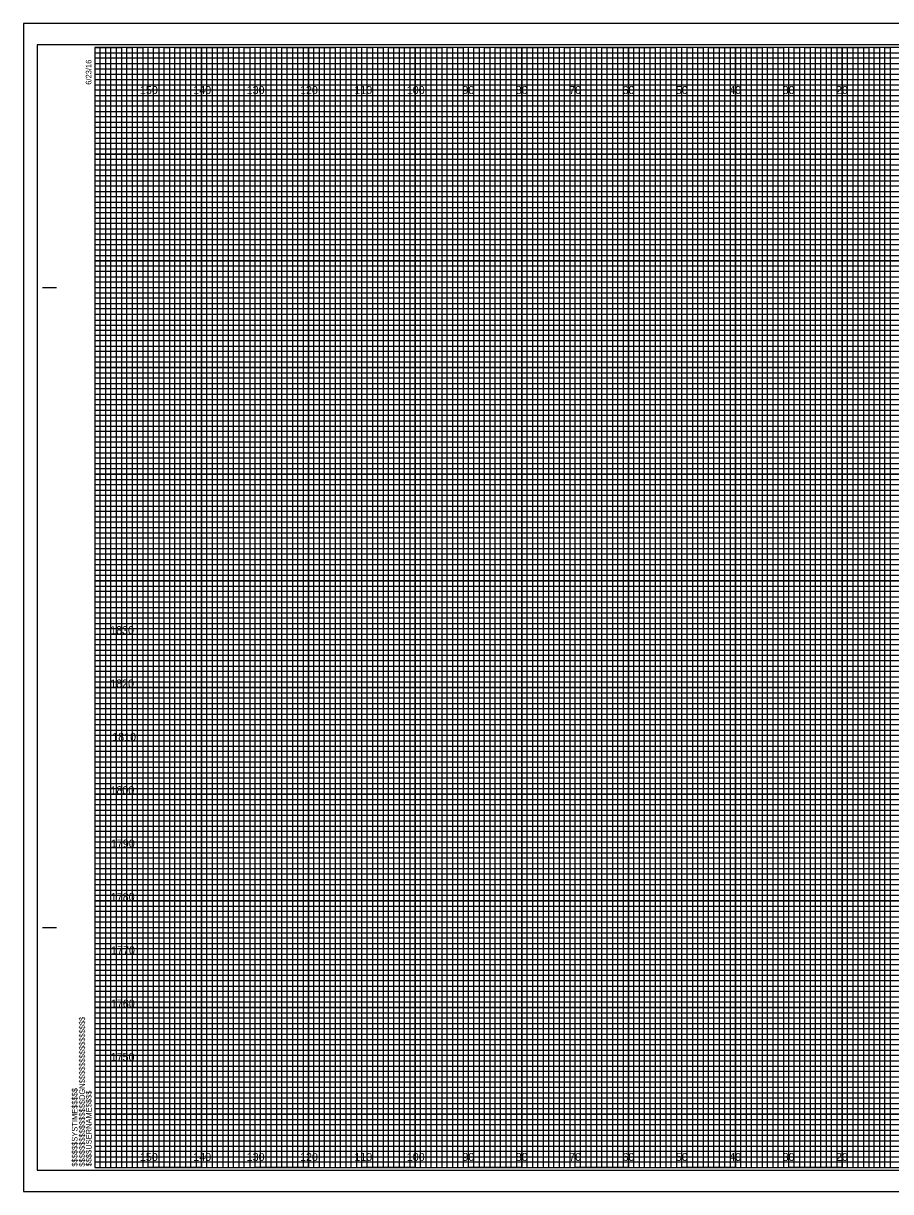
# Model space of a CAD drawing. Extents: x -13 to 323, y -5 to 654.
# Drawn here: x -13.4 to 149.1, y 435.5 to 654.5 of the extents above; entities that cross this region are included whole.
import ezdxf

# ---------------------------------------------------------------- set-up
doc = ezdxf.new("R2010")
doc.units = 0
for name, color, linetype in [('Prop XS DDE', 7, 'Continuous'), ('Prop XS Earthwork Shape', 7, 'Continuous'), ('Raster_Level_0', 7, 'Continuous'), ('Scratch_Level_3', 7, 'Continuous'), ('Sheet Cross Section CELL', 7, 'Continuous'), ('Sheet Cross Section Grid Minor 1 CELL', 7, 'Continuous'), ('Sheet Cross Section Grid Minor 2 CELL', 7, 'Continuous'), ('Sheet Cutting Line CELL', 7, 'Continuous'), ('Sheet DOT Grid CELL', 7, 'Continuous'), ('Sheet Plot Border Inside CELL', 7, 'Continuous'), ('Sheet Plot Border Outside CELL', 7, 'Continuous')]:
    doc.layers.add(name, color=color, linetype=linetype)

msp = doc.modelspace()

# ---------------------------------------------------------------- linework, layer by layer
at = {"layer": 'Prop XS DDE'}
for points in [[(0, 650), (5, 650), (5, 440), (15, 440), (15, 650), (25, 650), (25, 440), (35, 440), (35, 650), (45, 650), (45, 440), (55, 440), (55, 650), (65, 650), (65, 440), (75, 440), (75, 650), (85, 650), (85, 440), (95, 440), (95, 650), (105, 650), (105, 440), (115, 440), (115, 650), (125, 650), (125, 440), (135, 440), (135, 650), (145, 650), (145, 440), (155, 440)], [(0, 645), (275, 645)], [(0, 625), (320, 625), (320, 635), (0, 635)], [(0, 605), (320, 605), (320, 615), (0, 615)], [(0, 585), (320, 585), (320, 595), (0, 595)], [(0, 565), (320, 565), (320, 575), (0, 575)], [(0, 545), (320, 545), (320, 555), (0, 555)], [(0, 525), (320, 525), (320, 535), (0, 535)], [(0, 505), (320, 505), (320, 515), (0, 515)], [(0, 485), (320, 485), (320, 495), (0, 495)], [(0, 465), (320, 465), (320, 475), (0, 475)], [(0, 445), (320, 445), (320, 455), (0, 455)]]:
    msp.add_lwpolyline(points, dxfattribs=at)
at = {"layer": 'Prop XS Earthwork Shape'}
for p, q in [((10, 650), (0, 650)), ((10, 440), (10, 650)), ((30, 650), (20, 650)), ((20, 650), (20, 440)), ((30, 440), (30, 650)), ((50, 650), (40, 650)), ((40, 650), (40, 440)), ((50, 440), (50, 650)), ((70, 650), (60, 650)), ((60, 650), (60, 440)), ((70, 440), (70, 650)), ((90, 650), (80, 650)), ((80, 650), (80, 440)), ((90, 440), (90, 650)), ((110, 650), (100, 650)), ((100, 650), (100, 440)), ((110, 440), (110, 650)), ((130, 650), (120, 650)), ((120, 650), (120, 440)), ((130, 440), (130, 650)), ((150, 650), (140, 650)), ((140, 650), (140, 440)), ((20, 440), (10, 440)), ((40, 440), (30, 440)), ((60, 440), (50, 440)), ((80, 440), (70, 440)), ((100, 440), (90, 440)), ((120, 440), (110, 440)), ((140, 440), (130, 440))]:
    msp.add_line(p, q, dxfattribs=at)
for points in [[(0, 640), (320, 640), (320, 630), (0, 630)], [(0, 620), (320, 620), (320, 610), (0, 610)], [(0, 600), (320, 600), (320, 590), (0, 590)], [(0, 580), (320, 580), (320, 570), (0, 570)], [(0, 560), (320, 560), (320, 550), (0, 550)], [(0, 540), (320, 540), (320, 530), (0, 530)], [(0, 520), (320, 520), (320, 510), (0, 510)], [(0, 500), (320, 500), (320, 490), (0, 490)], [(0, 480), (320, 480), (320, 470), (0, 470)], [(0, 460), (320, 460), (320, 450), (0, 450)]]:
    msp.add_lwpolyline(points, dxfattribs=at)
at = {"layer": 'Sheet Cross Section CELL'}
for p, q in [((-9.8, 605), (-7.3, 605)), ((-9.7, 605), (-7.2, 605)), ((-9.8, 485), (-7.3, 485)), ((-9.7, 485), (-7.2, 485)), ((0, 440), (0, 440)), ((0, 440), (0, 440)), ((0, 440), (0, 440)), ((0, 440), (0, 440)), ((0, 440), (0, 440)), ((0, 440), (0, 440)), ((0, 440), (0, 440))]:
    msp.add_line(p, q, dxfattribs=at)
msp.add_lwpolyline([(320, 650), (0, 650), (0, 440), (320, 440)], close=True, dxfattribs=at)
at = {"layer": 'Sheet Cross Section Grid Minor 1 CELL'}
for p, q in [((0, 649), (260, 649)), ((260, 647.98), (0, 647.98)), ((0, 647.98), (0, 647)), ((0, 647), (260, 647)), ((260, 645.89), (0, 645.89)), ((0, 645.89), (0, 644)), ((0, 644), (320, 644))]:
    msp.add_line(p, q, dxfattribs=at)
for points in [[(0, 643), (270, 643), (320, 643), (320, 642), (0, 642)], [(0, 641), (320, 641), (320, 639), (0, 639)], [(0, 638), (320, 638), (320, 637), (0, 636.98)], [(0, 636), (320, 636), (320, 634), (0, 634)], [(0, 633), (320, 633), (320, 632), (0, 632)], [(0, 631), (320, 631), (320, 629), (0, 629)], [(0, 628), (320, 628), (320, 627), (0, 627)], [(0, 626), (320, 626), (320, 624), (0, 624)], [(0, 623), (320, 623), (320, 622), (0, 622)], [(0, 621), (320, 621), (320, 619), (0, 619)], [(0, 618), (320, 618), (320, 617), (0, 617)], [(0, 616), (320, 616), (320, 613.95), (320, 613), (320, 612), (0, 612)], [(0, 614), (320, 614), (320, 613), (0, 613)], [(0, 611), (320, 611), (320, 609), (0, 609.03)], [(0, 609.03), (320, 609), (320, 608), (0, 608)], [(0, 607), (320, 607), (320, 606), (0, 606)], [(0, 604), (320, 604), (320, 603), (0, 603)], [(0, 602), (320, 602), (320, 601), (0, 601)], [(-0.07, 598.89), (320, 598.89), (320, 597.88), (-0.07, 597.88)], [(0, 597), (320, 597), (320, 596), (0, 596)], [(0, 594), (320, 594), (320, 593), (0, 593)], [(0, 592), (320, 592), (320, 591), (0, 591)], [(0, 589), (320, 589), (320, 588), (0, 588)], [(0, 587), (320, 587), (320, 586), (0, 586)], [(0, 584), (320, 584), (320, 583), (0, 583)], [(0, 582), (320, 582), (320, 581), (0, 581)], [(0, 579), (320, 579), (319.99, 577.98), (0, 578)], [(0, 577), (320, 577), (320, 576), (0, 576)], [(0, 574), (320, 574), (320, 573), (0, 573)], [(0, 572), (320, 572), (320, 571), (0, 571)], [(0, 569), (320, 569), (320, 568), (0, 568)], [(0, 567), (320, 567), (320, 566), (0, 566)], [(0, 564), (320, 564), (320, 563), (0, 563)], [(0, 562), (320, 562), (320, 561), (0, 561)], [(0, 559), (320, 559), (320, 558), (0, 558)], [(0, 556.99), (320.07, 556.91), (320, 556), (0, 556)], [(0, 554), (320, 554), (320, 553), (0, 553)], [(0, 552), (320, 552), (320, 551), (0, 551)], [(0, 549), (320, 549), (320, 548), (0, 548)], [(0, 547), (320, 547), (320, 546), (0, 546)], [(0, 544), (320, 544), (320, 543), (0, 543)], [(0, 542), (320, 542), (320, 541), (0, 541)], [(0, 539), (320, 539), (320, 538), (0, 538)], [(0, 537), (320, 537), (320, 536), (0, 536)], [(0, 534), (320, 534), (320, 533), (0, 533)], [(0, 532), (320, 532), (320, 531), (0, 531)], [(0, 529), (320, 529), (320, 528), (0, 528)], [(0, 527), (320, 527), (320, 526), (0, 526)], [(0, 524), (320, 524), (320, 523), (0, 523)], [(0, 522), (320, 522), (320, 521), (0, 521)], [(0, 519), (320, 519), (319.99, 517.98), (0, 518)], [(0, 517), (320, 517), (320, 516), (0, 516)], [(0, 514), (320, 514), (320, 513), (0, 513)], [(0, 512), (320, 512), (320, 511), (0, 511)], [(0, 509), (320, 509), (320, 508), (0, 508)], [(0, 507), (320, 507), (320, 506), (0, 506)], [(0, 504), (320, 504), (320, 503), (0, 503)], [(0, 502), (320, 502), (320, 501), (0, 501)], [(0, 499), (320, 499), (320, 498), (0, 498)], [(0, 496.99), (320.07, 496.91), (320, 496), (0, 496)], [(0, 494), (320, 494), (320, 493), (0, 493)], [(0, 492), (320, 492), (320, 491), (0, 491)], [(0, 489), (320, 489), (320, 488), (0, 488)], [(0, 487), (320, 487), (320, 486), (0, 486)], [(0, 484), (320, 484), (320, 483), (0, 483)], [(0, 482), (320, 482), (320, 481), (0, 481)], [(0, 479), (320, 479), (320, 478), (0, 478)], [(0, 477), (320, 477), (320, 476), (0, 476)], [(0, 474), (320, 474), (320, 473), (0, 473)], [(0, 472), (320, 472), (320, 471), (0, 471)], [(0, 469), (320, 469), (320, 468), (0, 468)], [(0, 467), (320, 467), (320, 466), (0, 466)], [(0, 464), (320, 464), (320, 463), (0, 463)], [(0, 462), (320, 462), (320, 461), (0, 461)], [(0, 459), (320, 459), (320, 458), (0, 458)], [(0, 457), (320, 457), (320, 456), (0, 456)], [(0, 454), (320, 454), (320, 453), (0, 453)], [(0, 452), (320, 452), (320, 451), (0, 451)], [(0, 449), (320, 449), (320, 448), (0, 448)], [(0, 447), (320, 447), (320, 446), (0, 446)], [(0, 444), (320, 444), (320, 443), (0, 443)], [(0, 442), (320, 442), (320, 441), (0, 441)]]:
    msp.add_lwpolyline(points, dxfattribs=at)
at = {"layer": 'Sheet Cross Section Grid Minor 2 CELL'}
for points in [[(0, 440), (1, 440), (1, 650), (2, 650), (2, 440)], [(2, 440), (3, 440), (3, 650), (4, 650), (4, 440)], [(5, 440), (6, 440), (6, 650), (7, 650), (7, 440)], [(7, 440), (8, 440), (8, 650), (9, 650), (9, 440)], [(10, 440), (11, 440), (11, 650), (12, 650), (12, 440)], [(12, 440), (13, 440), (13, 650), (14, 650), (14, 440)], [(15, 440), (16, 440), (16, 650), (17, 650), (17, 440)], [(17, 440), (18, 440), (18, 650), (19, 650), (19, 440)], [(20, 440), (21, 440), (21, 650), (22, 650), (22, 440)], [(22, 440), (23, 440), (23, 650), (24, 650), (24, 440)], [(25, 440), (26, 440), (26, 650), (27, 650), (27, 440)], [(27, 440), (28, 440), (28, 650), (29, 650), (29, 440)], [(30, 440), (31, 440), (31, 650), (32, 650), (32, 440)], [(32, 440), (33, 440), (33, 650), (34, 650), (34, 440)], [(35, 440), (36, 440), (36, 650), (37, 650), (37, 440)], [(37, 440), (38, 440), (38, 650), (39, 650), (39, 440)], [(40, 440), (41, 440), (41, 650), (42, 650), (42, 440)], [(42, 440), (43, 440), (43, 650), (44, 650), (44, 440)], [(45, 440), (46, 440), (46, 650), (47, 650), (47, 440)], [(47, 440), (48, 440), (48, 650), (49, 650), (49, 440)], [(50, 440), (51, 440), (51, 650), (52, 650), (52, 440)], [(52, 440), (53, 440), (53, 650), (54, 650), (54, 440)], [(55, 440), (56, 440), (56, 650), (57, 650), (57, 440)], [(57, 440), (58, 440), (58, 650), (59, 650), (59, 440)], [(60, 440), (61, 440), (61, 650), (62, 650), (62, 440)], [(62, 440), (63, 440), (63, 650), (64, 650), (64, 440)], [(65, 440), (66, 440), (66, 650), (67, 650), (67, 440)], [(67, 440), (68, 440), (68, 650), (69, 650), (69, 440)], [(70, 440), (71, 440), (71, 650), (72, 650), (72, 440)], [(72, 440), (73, 440), (73, 650), (74, 650), (74, 440)], [(75, 440), (76, 440), (76, 650), (77, 650), (77, 440)], [(77, 440), (78, 440), (78, 650), (79, 650), (79, 440)], [(80, 440), (81, 440), (81, 650), (82, 650), (82, 440)], [(82, 440), (83, 440), (83, 650), (84, 650), (84, 440)], [(85, 440), (86, 440), (86, 650), (87, 650), (87, 440)], [(87, 440), (88, 440), (88, 650), (89, 650), (89, 440)], [(90, 440), (91, 440), (91, 650), (92, 650), (92, 440)], [(92, 440), (93, 440), (93, 650), (94, 650), (94, 440)], [(95, 440), (96, 440), (96, 650), (97, 650), (97, 440)], [(97, 440), (98, 440), (98, 650), (99, 650), (99, 440)], [(100, 440), (101, 440), (101, 650), (102, 650), (102, 440)], [(102, 440), (103, 440), (103, 650), (104, 650), (104, 440)], [(105, 440), (106, 440), (106, 650), (107, 650), (107, 440)], [(107, 440), (108, 440), (108, 650), (109, 650), (109, 440)], [(110, 440), (111, 440), (111, 650), (112, 650), (112, 440)], [(112, 440), (113, 440), (113, 650), (114, 650), (114, 440)], [(115, 440), (116, 440), (116, 650), (117, 650), (117, 440)], [(117, 440), (118, 440), (118, 650), (119, 650), (119, 440)], [(120, 440), (121, 440), (121, 650), (122, 650), (122, 440)], [(122, 440), (123, 440), (123, 650), (124, 650), (124, 440)], [(125, 440), (126, 440), (126, 650), (127, 650), (127, 440)], [(127, 440), (128, 440), (128, 650), (129, 650), (129, 440)], [(130, 440), (131, 440), (131, 650), (132, 650), (132, 440)], [(132, 440), (133, 440), (133, 650), (134, 650), (134, 440)], [(135, 440), (136, 440), (136, 650), (137, 650), (137, 440)], [(137, 440), (138, 440), (138, 650), (139, 650), (139, 440)], [(140, 440), (141, 440), (141, 650), (142, 650), (142, 440)], [(142, 440), (143, 440), (143, 650), (144, 650), (144, 440)], [(145, 440), (146, 440), (146, 650), (147, 650), (147, 440)], [(147, 440), (148, 440), (148, 650), (149, 650), (149, 440)]]:
    msp.add_lwpolyline(points, dxfattribs=at)
at = {"layer": 'Sheet Cutting Line CELL'}
for p, q in [((323.3, 654.5), (-13.4, 654.5)), ((-13.4, 654.5), (-13.4, 435.5)), ((-13.4, 435.5), (323.3, 435.5))]:
    msp.add_line(p, q, dxfattribs=at)
at = {"layer": 'Sheet DOT Grid CELL'}
for p, q in [((10, 440), (10, 650)), ((20, 440), (20, 650)), ((30, 440), (30, 650)), ((40, 440), (40, 650)), ((50, 440), (50, 650)), ((60, 440), (60, 650)), ((70, 440), (70, 650)), ((80, 440), (80, 650)), ((90, 440), (90, 650)), ((100, 440), (100, 650)), ((110, 440), (110, 650)), ((120, 440), (120, 650)), ((130, 440), (130, 650)), ((140, 440), (140, 650)), ((0, 640), (320, 640)), ((0, 630), (320, 630)), ((0, 620), (320, 620)), ((0, 610), (320, 610)), ((0, 600), (320, 600)), ((0, 590), (320, 590)), ((0, 580), (320, 580)), ((0, 570), (320, 570)), ((0, 560), (320, 560)), ((0, 550), (320, 550)), ((0, 540), (320, 540)), ((0, 530), (320, 530)), ((0, 520), (320, 520)), ((0, 510), (320, 510)), ((0, 500), (320, 500)), ((0, 490), (320, 490)), ((0, 480), (320, 480)), ((0, 470), (320, 470)), ((0, 460), (320, 460)), ((0, 450), (320, 450))]:
    msp.add_line(p, q, dxfattribs=at)
at = {"layer": 'Sheet Plot Border Inside CELL'}
msp.add_lwpolyline([(-10.8, 439.5), (322.4, 439.5), (322.4, 650.5), (-10.8, 650.5)], close=True, dxfattribs=at)
at = {"layer": 'Sheet Plot Border Outside CELL'}
msp.add_lwpolyline([(-13.4, 435.5), (323.3, 435.5), (323.3, 654.5), (-13.4, 654.5)], close=True, dxfattribs=at)

# ---------------------------------------------------------------- texts
at = {"layer": 'Raster_Level_0'}
for s, p in [('150', (8.44, 641.25)), ('140', (18.44, 641.25)), ('130', (28.44, 641.25)), ('120', (38.44, 641.25)), ('110', (48.62, 641.25)), ('100', (58.44, 641.25)), ('90', (68.86, 641.25)), ('80', (78.86, 641.25)), ('70', (88.86, 641.25)), ('60', (98.86, 641.25)), ('50', (108.86, 641.25)), ('40', (118.86, 641.25)), ('30', (128.86, 641.25)), ('20', (138.86, 641.25)), ('150', (8.44, 441.25)), ('140', (18.44, 441.25)), ('130', (28.44, 441.25)), ('120', (38.44, 441.25)), ('110', (48.62, 441.25)), ('100', (58.44, 441.25)), ('90', (68.86, 441.25)), ('80', (78.86, 441.25)), ('70', (88.86, 441.25)), ('60', (98.86, 441.25)), ('50', (108.86, 441.25)), ('40', (118.86, 441.25)), ('30', (128.86, 441.25)), ('20', (138.86, 441.25))]:
    msp.add_text(s, height=1.5, dxfattribs=at).set_placement(p)
at = {"layer": 'Scratch_Level_3'}
for s, p in [('1830', (2.86, 540)), ('1820', (2.87, 530)), ('1810', (3.25, 520)), ('1800', (2.92, 510)), ('1790', (3, 500)), ('1780', (2.98, 490)), ('1770', (3.04, 480)), ('1760', (3, 470)), ('1750', (2.96, 460))]:
    msp.add_text(s, height=1.5, dxfattribs=at).set_placement(p)
at = {"layer": 'Sheet Cross Section CELL'}
for s, p in [('6/23/16', (-0.65, 643)), ('$$$$$$$$$$$$$$$$DGN$$$$$$$$$$$$$$$$', (-1.88, 440.18)), ('$$$$$$SYSTIME$$$$$', (-3.26, 440.18)), ('$$$$USERNAME$$$$', (-0.62, 440.23))]:
    msp.add_text(s, height=1.05, rotation=90, dxfattribs=at).set_placement(p)

doc.saveas('drawing.dxf')
